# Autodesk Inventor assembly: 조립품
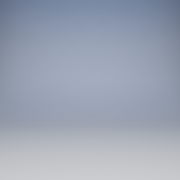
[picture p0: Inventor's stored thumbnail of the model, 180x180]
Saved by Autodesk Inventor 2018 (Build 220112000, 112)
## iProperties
Created: 2020-04
Part Number: 조립품
Document SubType Name: Assembly
Designer: 1class 18
Author: 1class 18
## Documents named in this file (1)
- C:\Users\1class 18\Desktop\700407V1036\조립품.iam
